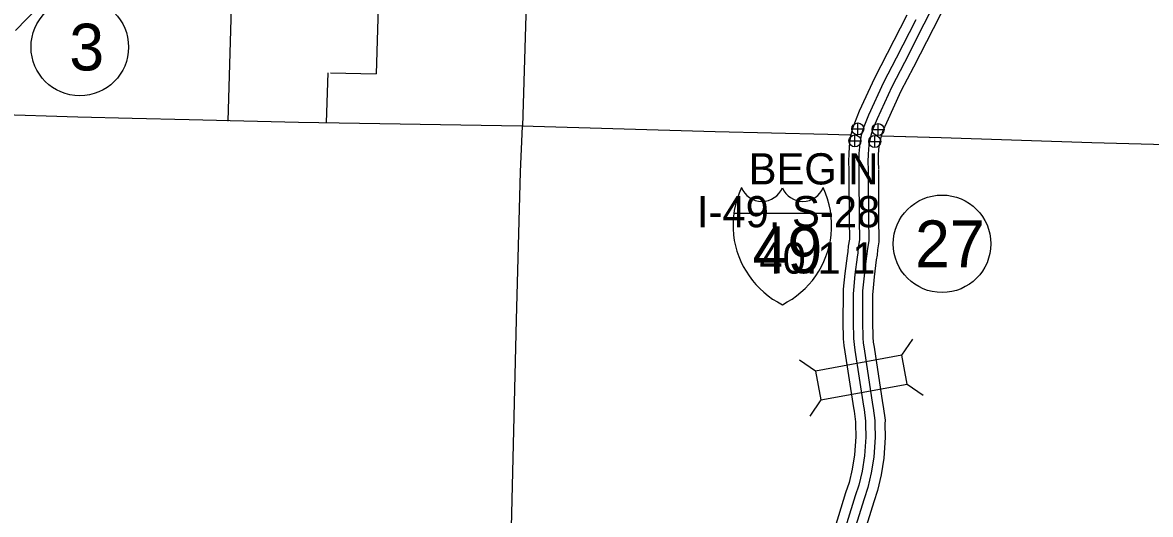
# Model space of a CAD drawing. Extents: x -939622 to -934245, y 1383184 to 1385301.
# Drawn here: x -936378.14 to -936332.35, y 1384770.09 to 1384790.08 of the extents above; entities that cross this region are included whole.
import ezdxf

# ---------------------------------------------------------------- set-up
doc = ezdxf.new("R2010")
doc.units = 0
for name, color, linetype in [('10', 7, 'Continuous'), ('19', 7, 'Continuous'), ('2', 7, 'Continuous'), ('25', 7, 'Continuous'), ('26', 7, 'Continuous'), ('27', 7, 'Continuous'), ('7', 7, 'Continuous'), ('8', 7, 'Continuous'), ('Level 19', 7, 'Continuous'), ('Level 2', 7, 'Continuous'), ('Level 20', 7, 'Continuous'), ('Level 23', 7, 'Continuous'), ('Level 26', 7, 'Continuous'), ('Level 27', 7, 'Continuous'), ('Level 8', 7, 'Continuous')]:
    doc.layers.add(name, color=color, linetype=linetype)

msp = doc.modelspace()

# ---------------------------------------------------------------- linework, layer by layer
at = {"layer": '10'}
msp.add_lwpolyline([(-936378.434, 1384789.755), (-936377.502, 1384790.7)], dxfattribs=at)
at = {"layer": '19'}
for points in [[(-936340.355, 1384792.328), (-936341.546, 1384790.012), (-936342.337, 1384788.455), (-936342.85, 1384787.47), (-936343.45, 1384786.169), (-936343.631, 1384785.713), (-936343.707, 1384785.489)], [(-936339.988, 1384792.141), (-936341.178, 1384789.824), (-936341.97, 1384788.266), (-936342.48, 1384787.288), (-936343.07, 1384786.006), (-936343.211, 1384785.674), (-936343.283, 1384785.477)], [(-936342.247, 1384790.37), (-936343.037, 1384788.815), (-936343.558, 1384787.817), (-936344.174, 1384786.479), (-936344.369, 1384785.988), (-936344.447, 1384785.764), (-936344.517, 1384785.512)], [(-936341.88, 1384790.182), (-936342.671, 1384788.626), (-936343.187, 1384787.635), (-936343.794, 1384786.316), (-936343.982, 1384785.844), (-936344.053, 1384785.639), (-936344.093, 1384785.5)]]:
    msp.add_lwpolyline(points, dxfattribs=at)
at = {"layer": '2'}
for points in [[(-936380.828, 1384786.399), (-936380.474, 1384786.389), (-936379.338, 1384786.351), (-936375.897, 1384786.25), (-936373.696, 1384786.189), (-936371.378, 1384786.132), (-936366.939, 1384786.025)], [(-936366.939, 1384786.025), (-936357.868, 1384785.877), (-936350.029, 1384785.643), (-936345.448, 1384785.539), (-936344.563, 1384785.513)], [(-936343.243, 1384785.476), (-936340.849, 1384785.407), (-936334.73, 1384785.201), (-936326.235, 1384784.972), (-936319.114, 1384784.775), (-936311.283, 1384784.553)]]:
    msp.add_lwpolyline(points, dxfattribs=at)
at = {"layer": '26'}
for p, q in [((-936344.476, 1384785.751), (-936343.988, 1384785.751)), ((-936344.232, 1384785.507), (-936344.232, 1384785.995)), ((-936343.654, 1384785.728), (-936343.166, 1384785.728)), ((-936343.41, 1384785.484), (-936343.41, 1384785.972))]:
    msp.add_line(p, q, dxfattribs=at)
for centre in [(-936344.232, 1384785.751), (-936343.41, 1384785.728)]:
    msp.add_circle(centre, 0.244, dxfattribs=at)
at = {"layer": '27'}
msp.add_circle((-936375.818, 1384789.079), 1.98, dxfattribs=at)
at = {"layer": '7'}
for points in [[(-936363.605, 1384793.864), (-936363.79, 1384787.992)], [(-936369.8, 1384786.069), (-936369.617, 1384792.087)], [(-936365.754, 1384788.032), (-936365.818, 1384786.013)], [(-936365.638, 1384788.029), (-936363.79, 1384787.989)]]:
    msp.add_lwpolyline(points, dxfattribs=at)
at = {"layer": '8'}
msp.add_lwpolyline([(-936357.375, 1384801.682), (-936357.85, 1384785.868)], dxfattribs=at)
at = {"layer": 'Level 19'}
for points in [[(-936344.517, 1384785.512), (-936344.563, 1384785.213), (-936344.6, 1384784.771), (-936344.608, 1384784.411), (-936344.597, 1384784.087)], [(-936344.093, 1384785.5), (-936344.154, 1384785.158), (-936344.188, 1384784.749), (-936344.195, 1384784.413), (-936344.184, 1384784.102)], [(-936343.707, 1384785.489), (-936343.782, 1384785.108), (-936343.813, 1384784.73), (-936343.82, 1384784.415), (-936343.81, 1384784.115)], [(-936343.283, 1384785.477), (-936343.372, 1384785.053), (-936343.401, 1384784.708), (-936343.408, 1384784.418), (-936343.397, 1384784.129)], [(-936344.597, 1384784.106), (-936344.588, 1384781.888), (-936344.574, 1384781.423), (-936344.575, 1384781.277), (-936344.624, 1384780.987), (-936344.641, 1384780.771), (-936344.669, 1384780.602), (-936344.76, 1384779.878), (-936344.823, 1384779.237), (-936344.832, 1384779.059), (-936344.834, 1384777.911), (-936344.82, 1384777.219), (-936344.794, 1384776.949), (-936344.758, 1384776.701), (-936344.409, 1384774.415), (-936344.381, 1384774.28), (-936344.327, 1384773.855), (-936344.328, 1384773.759), (-936344.318, 1384773.243), (-936344.369, 1384772.51), (-936344.464, 1384771.926), (-936344.589, 1384771.388), (-936344.729, 1384770.963), (-936345.356, 1384768.924)], [(-936344.185, 1384784.107), (-936344.175, 1384781.895), (-936344.161, 1384781.427), (-936344.163, 1384781.24), (-936344.215, 1384780.936), (-936344.231, 1384780.721), (-936344.261, 1384780.543), (-936344.35, 1384779.832), (-936344.411, 1384779.206), (-936344.42, 1384779.048), (-936344.422, 1384777.915), (-936344.408, 1384777.243), (-936344.385, 1384776.999), (-936344.35, 1384776.762), (-936344.003, 1384774.488), (-936343.974, 1384774.348), (-936343.914, 1384773.878), (-936343.916, 1384773.76), (-936343.905, 1384773.233), (-936343.959, 1384772.463), (-936344.059, 1384771.846), (-936344.192, 1384771.277), (-936344.336, 1384770.838), (-936344.955, 1384768.824)], [(-936343.81, 1384784.109), (-936343.8, 1384781.902), (-936343.786, 1384781.431), (-936343.788, 1384781.207), (-936343.842, 1384780.89), (-936343.859, 1384780.676), (-936343.89, 1384780.489), (-936343.977, 1384779.79), (-936344.037, 1384779.178), (-936344.045, 1384779.038), (-936344.047, 1384777.918), (-936344.033, 1384777.264), (-936344.012, 1384777.044), (-936343.979, 1384776.818), (-936343.634, 1384774.555), (-936343.603, 1384774.41), (-936343.539, 1384773.899), (-936343.541, 1384773.762), (-936343.53, 1384773.224), (-936343.586, 1384772.419), (-936343.691, 1384771.773), (-936343.83, 1384771.176), (-936343.978, 1384770.725), (-936344.591, 1384768.733)], [(-936343.397, 1384784.111), (-936343.388, 1384781.909), (-936343.373, 1384781.435), (-936343.376, 1384781.17), (-936343.432, 1384780.839), (-936343.449, 1384780.626), (-936343.481, 1384780.43), (-936343.567, 1384779.744), (-936343.626, 1384779.147), (-936343.632, 1384779.027), (-936343.634, 1384777.922), (-936343.621, 1384777.288), (-936343.602, 1384777.093), (-936343.571, 1384776.879), (-936343.227, 1384774.628), (-936343.196, 1384774.478), (-936343.126, 1384773.922), (-936343.128, 1384773.763), (-936343.117, 1384773.214), (-936343.176, 1384772.372), (-936343.286, 1384771.693), (-936343.433, 1384771.065), (-936343.585, 1384770.6), (-936344.19, 1384768.633)]]:
    msp.add_lwpolyline(points, dxfattribs=at)
at = {"layer": 'Level 2'}
for points in [[(-936382.911, 1384786.452), (-936381.612, 1384786.423), (-936380.474, 1384786.389), (-936379.338, 1384786.351), (-936375.897, 1384786.25), (-936373.696, 1384786.189), (-936371.378, 1384786.132), (-936366.939, 1384786.025)], [(-936366.939, 1384786.025), (-936357.868, 1384785.877), (-936350.029, 1384785.643), (-936345.448, 1384785.539), (-936344.539, 1384785.513)], [(-936343.261, 1384785.476), (-936340.849, 1384785.407), (-936334.73, 1384785.201), (-936326.235, 1384784.972), (-936319.114, 1384784.775), (-936311.283, 1384784.553)]]:
    msp.add_lwpolyline(points, dxfattribs=at)
at = {"layer": 'Level 20'}
for p, q in [((-936342.443, 1384776.555), (-936341.994, 1384777.208)), ((-936345.947, 1384775.906), (-936346.6, 1384776.355)), ((-936342.227, 1384775.387), (-936341.574, 1384774.938)), ((-936345.731, 1384774.738), (-936346.18, 1384774.085))]:
    msp.add_line(p, q, dxfattribs=at)
msp.add_lwpolyline([(-936345.731, 1384774.738), (-936342.227, 1384775.387), (-936342.443, 1384776.555), (-936345.947, 1384775.906)], close=True, dxfattribs=at)
at = {"layer": 'Level 23'}
msp.add_line((-936349.261, 1384782.336), (-936345.328, 1384782.336), dxfattribs=at)
for centre, radius, start, end in [((-936345.606, 1384781.823), 3.69, 155.2204, 185.7928), ((-936348.124, 1384783.709), 0.899, 202.1459, 337.3414), ((-936346.465, 1384783.709), 0.899, 202.6586, 337.8541), ((-936348.983, 1384781.823), 3.69, 354.2072, 24.7796), ((-936345.674, 1384781.855), 3.626, 186.3923, 243.4571), ((-936348.915, 1384781.855), 3.626, 296.5429, 353.6077)]:
    msp.add_arc(centre, radius, start, end, dxfattribs=at)
at = {"layer": 'Level 26'}
for p, q in [((-936344.59, 1384785.264), (-936344.103, 1384785.264)), ((-936344.347, 1384785.021), (-936344.347, 1384785.508)), ((-936343.79, 1384785.241), (-936343.303, 1384785.241)), ((-936343.546, 1384784.997), (-936343.546, 1384785.485))]:
    msp.add_line(p, q, dxfattribs=at)
for centre in [(-936344.347, 1384785.264), (-936343.546, 1384785.241)]:
    msp.add_circle(centre, 0.244, dxfattribs=at)
at = {"layer": 'Level 27'}
msp.add_circle((-936340.81, 1384781.085), 1.98, dxfattribs=at)
at = {"layer": 'Level 8'}
for points in [[(-936357.923, 1384784.014), (-936357.85, 1384785.868)], [(-936366.604, 1384738.715), (-936359.058, 1384738.51), (-936358.882, 1384746.135), (-936358.677, 1384754.01), (-936358.466, 1384762.524), (-936358.284, 1384770.12), (-936358.082, 1384777.994), (-936357.923, 1384784.014)]]:
    msp.add_lwpolyline(points, dxfattribs=at)

# ---------------------------------------------------------------- texts
at = {"layer": '25'}
for s, p in [('BEGIN', (-936348.663, 1384783.497)), ('I-49, S-28', (-936350.763, 1384781.757)), ('40.1 1', (-936348.228, 1384779.873))]:
    msp.add_text(s, height=1.2672, dxfattribs=at).set_placement(p)
at = {"layer": '27'}
msp.add_text('3', height=1.901, dxfattribs=at).set_placement((-936376.243, 1384788.128))
at = {"layer": 'Level 23'}
msp.add_text('49', height=1.9008, dxfattribs=at).set_placement((-936348.501, 1384779.89))
at = {"layer": 'Level 27'}
msp.add_text('27', height=1.9008, dxfattribs=at).set_placement((-936341.908, 1384780.134))

doc.saveas('drawing.dxf')
